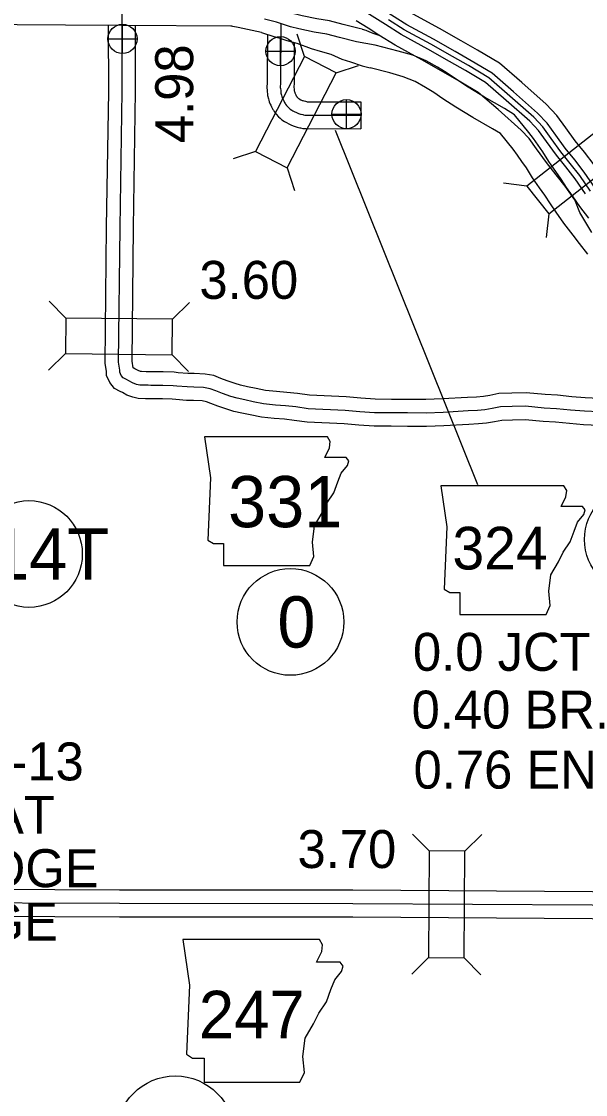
# Model space of a CAD drawing. Extents: x 31699 to 244310, y -8841 to 11474.
# Drawn here: x 96834 to 97253, y 3295 to 4091 of the extents above; entities that cross this region are included whole.
import ezdxf

# ---------------------------------------------------------------- set-up
doc = ezdxf.new("R2010")
doc.units = 0
for name, color, linetype in [('B_Logo', 7, 'Continuous'), ('G-ANNO-TEXT', 7, 'Continuous'), ('Level 21', 7, 'Continuous'), ('New Level (0)', 7, 'Continuous'), ('R_Border Notes', 7, 'Continuous'), ('R_XS_EARTHWORK_STAGE1', 7, 'Continuous'), ('R_XS_EARTHWORK_STAGE2', 7, 'Continuous'), ('S_AREA_CALC', 7, 'Continuous'), ('S_WALL', 7, 'Continuous'), ('S_WALL_ANNOT', 7, 'Continuous')]:
    doc.layers.add(name, color=color, linetype=linetype)

msp = doc.modelspace()

# ---------------------------------------------------------------- linework, layer by layer
at = {"layer": 'B_Logo'}
for points in [[(97262.64, 3801.32), (97251.78, 3801.84), (97241.59, 3802.64), (97231.06, 3803.77), (97221.87, 3804.25), (97208.14, 3805.54), (97198.22, 3805.34), (97189.44, 3805.03), (97183.47, 3803.81), (97178.02, 3803), (97172.44, 3802.46), (97165.59, 3802.11), (97146.9, 3800.99), (97134.39, 3800.49), (97120.61, 3800.58), (97108.5, 3800.69), (97096.12, 3800.79), (97085.13, 3801.51), (97074.26, 3802.5), (97046.89, 3803.75), (97037.76, 3805.03), (97030.09, 3805.86), (97022.5, 3806.5), (97013.57, 3807.31), (97005.96, 3808.88), (96999.69, 3810.34), (96994.15, 3811.46), (96989.54, 3812.87), (96983.25, 3814.99), (96978.3, 3816.93), (96974.09, 3818.61), (96969.22, 3819.48), (96961.96, 3819.85), (96956.97, 3819.92), (96949.44, 3820.49), (96946.64, 3820.79), (96938.98, 3821.09), (96933.72, 3821.08), (96929.93, 3821.1), (96928, 3821.14), (96926.4, 3821.19), (96921.87, 3821.33), (96919.47, 3821.83), (96916.46, 3822.99), (96913.64, 3824.56), (96911.9, 3825.4), (96909.62, 3826.64), (96908.14, 3828.42), (96907.11, 3830.81), (96907.02, 3832.42), (96906.15, 3838.21), (96907.19, 3938.31), (96908.76, 4039.09), (96908.66, 4098.18)], [(97255.13, 3945.1), (97248.36, 3953.83), (97242.94, 3961.64), (97238.6, 3967.86), (97234.46, 3974.14), (97230.52, 3979.83), (97225.31, 3987.11), (97220.89, 3994.26), (97217.5, 3999.23), (97214.1, 4004.26), (97210.65, 4008.82), (97200.03, 4021.9), (97192.59, 4026.54), (97177.7, 4034.96), (97165.43, 4042.27), (97156.16, 4048.49), (97149.18, 4053.21), (97142.74, 4057.26), (97134.29, 4061.89), (97124.46, 4065.97), (97113.7, 4068.97), (97096.47, 4073.55), (97082.6, 4075.97), (97070.11, 4079.21), (97060.62, 4081.75), (97051.36, 4083.1), (97039.94, 4085.55), (97033.66, 4087.21), (97023.24, 4090.47), (97014.49, 4092.76)], [(97026.63, 4089.45), (97026.36, 4045.61), (97026.1, 4042.13), (97026.18, 4041.4), (97026.41, 4039.8), (97026.5, 4038.6), (97026.58, 4037.87), (97026.95, 4036.34), (97027.23, 4035.47), (97027.45, 4034.68), (97027.73, 4034.01), (97027.93, 4033.62), (97028.63, 4032.23), (97029.32, 4030.84), (97029.67, 4030.31), (97030.01, 4029.65), (97030.7, 4028.73), (97031.79, 4027.62), (97032.74, 4026.77), (97033.55, 4026.05), (97034.57, 4025.34), (97035.45, 4024.82), (97036.86, 4024.11), (97037.74, 4023.67), (97038.55, 4023.21), (97039.62, 4022.84), (97041.03, 4022.4), (97041.63, 4022.28), (97042.77, 4022.03), (97043.38, 4021.91), (97044.38, 4021.67), (97045.65, 4021.56), (97085.88, 4021.46)], [(97256.41, 3965.09), (97248.33, 3976.86), (97241.36, 3985.72), (97234.33, 3994.44), (97227.15, 4004.36), (97221.05, 4012.89), (97214.17, 4020.08), (97196.53, 4035.67), (97180.84, 4049.29), (97165.69, 4058.3), (97153.82, 4065.09), (97137.73, 4074.22), (97118.02, 4084.98), (97106.41, 4092.31)], [(97423.97, 3434.48), (97257.68, 3435.28), (97079.99, 3436.43), (96906.84, 3436.56), (96762.45, 3437.22), (96696.17, 3438.85)]]:
    msp.add_lwpolyline(points, dxfattribs=at)
at = {"layer": 'G-ANNO-TEXT'}
msp.add_lwpolyline([(97066.96, 4010.43), (97172.49, 3747.61)], dxfattribs=at)
for points in [[(96969.84, 3782.88), (96974.41, 3752.42), (96972.38, 3706.24), (96976.44, 3703.7), (96984.05, 3703.7), (96984.05, 3687.46), (97048, 3687.46), (97051.05, 3694.06), (97050.03, 3704.72), (97051.56, 3716.9), (97057.14, 3726.54), (97060.69, 3733.65), (97065.77, 3741.26), (97068.81, 3749.38), (97071.35, 3755.98), (97075.92, 3761.56), (97076.93, 3765.11), (97074.9, 3767.65), (97059.17, 3767.65), (97062.72, 3774.76), (97063.23, 3779.32), (97061.13, 3782.83)], [(97145.26, 3746.52), (97149.83, 3716.07), (97147.8, 3669.88), (97151.86, 3667.34), (97159.48, 3667.34), (97159.48, 3651.1), (97223.43, 3651.1), (97226.47, 3657.7), (97225.46, 3668.36), (97226.98, 3680.54), (97232.56, 3690.18), (97236.11, 3697.29), (97241.19, 3704.9), (97244.23, 3713.02), (97246.77, 3719.62), (97251.34, 3725.2), (97252.35, 3728.75), (97250.32, 3731.29), (97234.59, 3731.29), (97238.14, 3738.4), (97238.65, 3742.97), (97236.55, 3746.47)], [(96953.75, 3409.97), (96958.83, 3376.14), (96956.57, 3324.82), (96961.08, 3322), (96969.54, 3322), (96969.54, 3303.95), (97040.6, 3303.95), (97043.98, 3311.28), (97042.85, 3323.13), (97044.55, 3336.66), (97050.75, 3347.38), (97054.7, 3355.27), (97060.34, 3363.73), (97063.72, 3372.75), (97066.54, 3380.08), (97071.62, 3386.29), (97072.74, 3390.23), (97070.49, 3393.05), (97053.01, 3393.05), (97056.95, 3400.95), (97057.52, 3406.02), (97055.18, 3409.92)]]:
    msp.add_lwpolyline(points, close=True, dxfattribs=at)
at = {"layer": 'Level 21'}
for p, q in [((96909.02, 4067.31), (96909.02, 4088.97)), ((96898.19, 4078.14), (96919.86, 4078.14)), ((97026.26, 4058.19), (97026.26, 4079.86)), ((97015.42, 4069.02), (97037.09, 4069.02)), ((97075.28, 4011.46), (97075.28, 4033.13)), ((97064.44, 4022.3), (97086.11, 4022.3))]:
    msp.add_line(p, q, dxfattribs=at)
for centre in [(96909.02, 4078.14), (97026.26, 4069.02), (97075.28, 4022.3)]:
    msp.add_circle(centre, 10.83, dxfattribs=at)
at = {"layer": 'New Level (0)'}
for points in [[(97259.08, 3984.76), (97251.79, 3994.03), (97244.93, 4002.54), (97237.97, 4012.15), (97231.34, 4021.42), (97223.41, 4029.7), (97205.31, 4045.7), (97188.68, 4060.14), (97172.4, 4069.82), (97160.42, 4076.67), (97144.21, 4085.87), (97124.78, 4096.48), (97113.53, 4103.58), (97105.51, 4108.64), (97096.06, 4114.53), (97077.98, 4124.53), (97070.02, 4129.4), (97063.11, 4133.48), (97055.17, 4138.45), (97041.49, 4148.32), (97037.44, 4151.42), (97032.18, 4155.6), (97028.91, 4158.29)], [(97260.09, 3967.08), (97251.69, 3979.33), (97244.62, 3988.32), (97237.64, 3996.97), (97230.53, 4006.79), (97224.26, 4015.56), (97217.06, 4023.09), (97199.27, 4038.81), (97183.29, 4052.68), (97167.79, 4061.9), (97155.88, 4068.71), (97139.75, 4077.86), (97120.13, 4088.57), (97108.64, 4095.83), (97100.64, 4100.87), (97091.42, 4106.62), (97073.37, 4116.61), (97065.3, 4121.55), (97058.34, 4125.65), (97050.05, 4130.85), (97036.03, 4140.96), (97031.81, 4144.18), (97026.42, 4148.47), (97023.02, 4151.26)], [(97252.72, 3963.09), (97244.97, 3974.39), (97238.11, 3983.12), (97231.02, 3991.91), (97223.77, 4001.93), (97217.83, 4010.23), (97211.28, 4017.07), (97193.78, 4032.54), (97178.39, 4045.9), (97163.59, 4054.7), (97151.76, 4061.47), (97135.7, 4070.58), (97115.91, 4081.39), (97104.19, 4088.78), (97096.21, 4093.81), (97087.19, 4099.44), (97069.17, 4109.41), (97061.01, 4114.4), (97054.01, 4118.53), (97045.4, 4123.93), (97031.07, 4134.27), (97026.69, 4137.61), (97021.18, 4141.99), (97017.67, 4144.87)], [(97257.31, 3934.4), (97248.5, 3949.35), (97244.62, 3958.69), (97237.58, 3968.96), (97230.94, 3977.41), (97223.73, 3986.34), (97216.32, 3996.57), (97210.76, 4004.36), (97204.92, 4010.46), (97187.74, 4025.64), (97173, 4038.44), (97158.97, 4046.78), (97147.22, 4053.5), (97131.24, 4062.57), (97111.26, 4073.48), (97099.3, 4081.03), (97091.34, 4086.05), (97082.54, 4091.53)]]:
    msp.add_lwpolyline(points, dxfattribs=at)
at = {"layer": 'R_Border Notes'}
for centre, radius in [((97291.42, 3706.72), 39.6), ((96839.61, 3695.97), 39.6), ((97033.65, 3645.54), 39.6), ((96948.25, 3264.65), 44)]:
    msp.add_circle(centre, radius, dxfattribs=at)
at = {"layer": 'R_XS_EARTHWORK_STAGE1'}
for p, q in [((97043.99, 4064.97), (97038.6, 4081.72)), ((97067.48, 4052.91), (97084.23, 4058.3)), ((97007.83, 3994.5), (96991.08, 3989.11)), ((97031.32, 3982.45), (97036.71, 3965.69)), ((97209.16, 3968.99), (97191.68, 3971.07)), ((97225.49, 3948.24), (97223.4, 3930.77)), ((96866.89, 3871.05), (96854.57, 3883.63)), ((96946.08, 3870.23), (96958.66, 3882.54)), ((96866.61, 3844.66), (96854.04, 3832.34)), ((96945.81, 3843.83), (96958.12, 3831.26)), ((97136.7, 3475.66), (97124.34, 3488.19)), ((97163.1, 3475.49), (97175.63, 3487.86)), ((97136.19, 3396.47), (97123.67, 3384.1)), ((97162.59, 3396.3), (97174.96, 3383.77))]:
    msp.add_line(p, q, dxfattribs=at)
for points in [[(97031.32, 3982.45), (97067.48, 4052.91), (97043.99, 4064.97), (97007.83, 3994.5)], [(97271.39, 4017.97), (97209.16, 3968.99), (97225.49, 3948.24), (97287.72, 3997.23)], [(96946.08, 3870.23), (96866.89, 3871.05), (96866.61, 3844.66), (96945.81, 3843.83)], [(97136.7, 3475.66), (97136.19, 3396.47), (97162.59, 3396.3), (97163.1, 3475.49)]]:
    msp.add_lwpolyline(points, close=True, dxfattribs=at)
at = {"layer": 'R_XS_EARTHWORK_STAGE2'}
msp.add_line((97085.9, 4031.46), (97085.86, 4011.46), dxfattribs=at)
for points in [[(97262.41, 3791.32), (97251.15, 3791.86), (97240.66, 3792.68), (97230.26, 3793.8), (97221.14, 3794.28), (97207.77, 3795.53), (97198.5, 3795.34), (97190.63, 3795.06), (97185.2, 3793.96), (97179.24, 3793.08), (97173.18, 3792.49), (97166.14, 3792.12), (97147.39, 3791), (97134.56, 3790.49), (97120.54, 3790.58), (97108.41, 3790.69), (97095.75, 3790.79), (97084.34, 3791.54), (97073.58, 3792.53), (97045.97, 3793.78), (97036.52, 3795.1), (97029.14, 3795.91), (97021.63, 3796.53), (97012.1, 3797.41), (97003.82, 3799.11), (96997.56, 3800.56), (96991.68, 3801.76), (96986.48, 3803.35), (96979.83, 3805.59), (96974.63, 3807.63), (96971.33, 3808.95), (96968.08, 3809.53), (96961.63, 3809.86), (96956.52, 3809.93), (96948.53, 3810.53), (96945.91, 3810.81), (96938.79, 3811.09), (96933.7, 3811.08), (96929.8, 3811.1), (96927.75, 3811.14), (96926.1, 3811.19), (96920.68, 3811.36), (96916.63, 3812.21), (96912.21, 3813.91), (96909.03, 3815.68), (96907.33, 3816.51), (96903.17, 3818.77), (96899.53, 3823.14), (96897.22, 3828.49), (96897.06, 3831.4), (96896.14, 3837.52), (96897.19, 3938.44), (96898.76, 4039.16), (96898.68, 4087.96)], [(97262.86, 3811.32), (97252.41, 3811.82), (97242.51, 3812.6), (97231.85, 3813.74), (97222.59, 3814.23), (97208.51, 3815.55), (97197.94, 3815.34), (97188.26, 3814.99), (97181.74, 3813.66), (97176.81, 3812.93), (97171.69, 3812.44), (97165.03, 3812.09), (97146.4, 3810.98), (97134.22, 3810.49), (97120.69, 3810.58), (97108.58, 3810.69), (97096.49, 3810.79), (97085.91, 3811.48), (97074.95, 3812.48), (97047.82, 3813.71), (97038.99, 3814.95), (97031.05, 3815.82), (97023.37, 3816.46), (97015.04, 3817.22), (97008.1, 3818.65), (97001.81, 3820.11), (96996.61, 3821.17), (96992.6, 3822.39), (96986.68, 3824.39), (96981.98, 3826.23), (96976.85, 3828.28), (96970.36, 3829.44), (96962.28, 3829.85), (96957.41, 3829.92), (96950.34, 3830.45), (96947.36, 3830.77), (96939.17, 3831.09), (96933.74, 3831.08), (96930.06, 3831.1), (96928.25, 3831.14), (96926.7, 3831.18), (96923.06, 3831.3), (96922.31, 3831.45), (96920.71, 3832.07), (96918.26, 3833.43), (96916.88, 3834.1), (96916.15, 3838.91), (96917.19, 3938.18), (96918.76, 4039.02), (96918.68, 4087.7)], [(97016.58, 4081.34), (97016.36, 4046.02), (97016.06, 4041.96), (97016.26, 4040.13), (97016.46, 4038.71), (97016.54, 4037.67), (97016.71, 4036.15), (97017.32, 4033.61), (97017.65, 4032.6), (97017.97, 4031.41), (97018.68, 4029.74), (97019.03, 4029.06), (97019.69, 4027.76), (97020.64, 4025.86), (97021.03, 4025.25), (97021.52, 4024.31), (97023.08, 4022.22), (97024.88, 4020.38), (97026.1, 4019.29), (97027.35, 4018.19), (97029.15, 4016.92), (97030.67, 4016.03), (97032.35, 4015.19), (97033.02, 4014.85), (97034.42, 4014.06), (97036.48, 4013.34), (97038.56, 4012.7), (97039.6, 4012.48), (97040.74, 4012.24), (97041.2, 4012.15), (97042.76, 4011.77), (97045.22, 4011.56), (97085.86, 4011.46)], [(97036.54, 4075.26), (97036.36, 4045.2), (97036.14, 4042.36), (97036.36, 4040.89), (97036.46, 4039.57), (97036.58, 4039.06), (97036.81, 4038.35), (97036.89, 4038.07), (97037.57, 4036.7), (97038.01, 4035.82), (97038.3, 4035.38), (97038.44, 4035.12), (97038.7, 4034.85), (97039.38, 4034.25), (97039.76, 4033.91), (97039.99, 4033.75), (97040.22, 4033.62), (97041.38, 4033.04), (97042.45, 4032.48), (97042.67, 4032.36), (97042.77, 4032.33), (97043.51, 4032.1), (97043.66, 4032.07), (97044.8, 4031.83), (97045.55, 4031.67), (97046, 4031.56), (97046.08, 4031.56), (97085.9, 4031.46)], [(97415.66, 3444.52), (97257.73, 3445.28), (97080.02, 3446.43), (96906.87, 3446.56), (96762.6, 3447.22), (96696.42, 3448.85)], [(97432.29, 3424.43), (97257.62, 3425.28), (97079.95, 3426.43), (96906.81, 3426.56), (96762.31, 3427.22), (96695.92, 3428.86)]]:
    msp.add_lwpolyline(points, dxfattribs=at)
at = {"layer": 'S_AREA_CALC'}
for points in [[(97086.78, 4085.39), (97084.71, 4085.75), (97072.66, 4088.88), (97062.65, 4091.56), (97053.13, 4092.95), (97042.27, 4095.28), (97036.43, 4096.82), (97026, 4100.09), (97016.74, 4102.51), (96998.9, 4106.08)], [(96994.77, 4086.51), (96991.02, 4087.42), (96990.23, 4087.52), (96989.51, 4087.58), (96908.6, 4088.18), (96866.74, 4088.43), (96759, 4089.01), (96727.57, 4089.46), (96724.41, 4089.31), (96720.46, 4088.71), (96713.6, 4087.88), (96684.86, 4087.43)], [(97012.24, 4083.01), (96994.77, 4086.51)], [(97086.78, 4085.39), (97089.59, 4084.54), (97092.41, 4083.47), (97095.62, 4082.13), (97099.3, 4081.03)], [(97012.24, 4083.01), (97021.21, 4079.99), (97024.96, 4078.91), (97031, 4076.9), (97038.51, 4074.89), (97048.96, 4071), (97055.8, 4069.12), (97063.71, 4066.71), (97071.76, 4063.23), (97078.19, 4061.08), (97086.91, 4058.26), (97092.82, 4056.73)], [(97254.24, 3918.35), (97248.08, 3926.35), (97243.41, 3932.62), (97236.55, 3941.47), (97230.98, 3949.49), (97226.57, 3955.81), (97222.41, 3962.11), (97218.59, 3967.64), (97213.22, 3975.13), (97208.75, 3982.37), (97205.47, 3987.17), (97202.21, 3992), (97199.03, 3996.21), (97189.57, 4007.86), (97183.72, 4011.5), (97168.92, 4019.87), (97156.32, 4027.38), (97146.82, 4033.76), (97139.96, 4038.4), (97133.91, 4042.2), (97126.21, 4046.43), (97117.43, 4050.06), (97107.32, 4052.88), (97092.82, 4056.73)]]:
    msp.add_lwpolyline(points, dxfattribs=at)

# ---------------------------------------------------------------- texts
at = {"layer": 'G-ANNO-TEXT'}
for s, height, p in [('331', 38.016, (96987.36, 3715.82)), ('324', 31.68, (97153.89, 3684.47)), ('247', 35.2, (96965.69, 3336.66))]:
    msp.add_text(s, height=height, dxfattribs=at).set_placement(p)
at = {"layer": 'R_Border Notes'}
for s, height, p in [('14T', 38.016, (96811.5, 3676.96)), ('0', 38.02, (97023.97, 3626.54))]:
    msp.add_text(s, height=height, dxfattribs=at).set_placement(p)
at = {"layer": 'S_WALL'}
for s, p in [('3.60', (96966.12, 3885.26)), ('0.40 BR.', (97123.58, 3566.43)), ('3.70', (97038.91, 3462.95))]:
    msp.add_text(s, height=28.16, dxfattribs=at).set_placement(p)
at = {"layer": 'S_WALL_ANNOT'}
msp.add_text('4.98', height=28.16, rotation=90, dxfattribs=at).set_placement((96961.47, 4000.78))
for s, height, p in [('0.0 JCT. 64', 28.1599, (97124.59, 3609.28)), ('S.H. 7, S-13', 28.1599, (96675.17, 3527.97)), ('0.76 END', 28.16, (97125.04, 3521.87)), ('ENDS AT', 28.16, (96695.64, 3488.36)), ('TRAIL EDGE', 28.16, (96667.4, 3448.75)), ('BRIDGE', 28.16, (96716.74, 3409.14))]:
    msp.add_text(s, height=height, dxfattribs=at).set_placement(p)

doc.saveas('drawing.dxf')
